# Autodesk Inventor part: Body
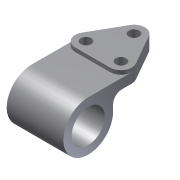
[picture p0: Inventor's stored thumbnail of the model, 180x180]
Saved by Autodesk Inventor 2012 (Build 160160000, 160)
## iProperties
Created: 2010-03
Part Number: Body
Document SubType Name: Modeling
Designer: bhakira
Density: 1 g/cm^3
Material: Default
Author: bhakira
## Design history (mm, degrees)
sketch "Sketch1"
  geometry: L1 (10.853, 41.202)-(30.853, 6.202); L2 (-10.853, 41.202)-(-30.853, 6.202); L3 (-20, -12.5)-(20, -12.5); C1 r 6 at (0, 35); A1 r 12.5 centre (0, 35) between (10.853, 41.202) and (-10.853, 41.202); A2 r 12.5 centre (-20, 0) between (-30.853, 6.202) and (-20, -12.5); A3 r 12.5 centre (20, 0) between (20, -12.5) and (30.853, 6.202); 1 further point
  constraints: 6 end point, 6 point on circle, 6 tangent, 4 centre point, 3 horizontal alignment, 2 equal radius, 1 coincident, 1 vertical alignment, 1 other
  dimensions: "d25" = 35 vertical distance of A1.centre A2.centre; "d27" = 12.5 radius of A1; "d28" = 40 distance of A3.centre A2.centre; "d29" = 20 horizontal distance of A3.centre A1.centre
extrude "Extrusion1" new body sketch "Sketch1" distance "d6" = 15.875; taper "d7" = 0 deg
workplane "Work Plane2"
workplane "Work Plane3"
sketch "Sketch2"
  geometry: L1 (0, 11.375)-(0, 0); L2 (-12.5, 15.875)-(6.202, 15.875) reference; L3 (-50, 11.375)-(0, 11.375); L4 (0, 0)-(-11.5, 0); L5 (-21.5, -17.125)-(-21.5, -10); C1 r 19 at (-50, -17.125); A1 r 28.5 centre (-50, -17.125) between (-50, 11.375) and (-21.5, -17.125); A2 r 10 centre (-11.5, -10) between (-11.5, 0) and (-21.5, -10)
  constraints: 8 end point, 4 point on circle, 4 tangent, 3 centre point, 1 coincident, 1 perpendicular
  dimensions: "d9" = 38 diameter of C1; "d10" = 57 diameter of A1; "d11" = 50 distance from line of L1 C1.centre; "d12" = 33 distance from line of C1.centre L2; "d13" = 10 radius of A2
extrude "Extrusion2" join sketch "Sketch2" stored distance "d14" = 63.5; taper "d15" = 0 deg
sketch "Sketch3"
  geometry: C1 r 6 at (20, 0) reference; C2 r 6 at (-20, 0) reference; C3 r 6 at (0, 35); 1 further point
  constraints: 1 centre point
extrude "Extrusion3" cut sketch "Sketch3" distance "d16" = 63.5; taper "d17" = 0 deg
node "Sketch4"
hole "Hole1" diameter "d32" = 12; stored, may be unused: countersink angle "d36" = 90 deg, drill point angle "d38" = 118 deg; dims "d33" = 6, "d34" = 4, "d35" = 2082.8, "d37" = 8, "d39" = 10, "d40" = 10
body "Solid1"
